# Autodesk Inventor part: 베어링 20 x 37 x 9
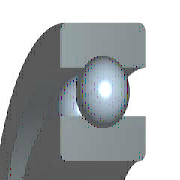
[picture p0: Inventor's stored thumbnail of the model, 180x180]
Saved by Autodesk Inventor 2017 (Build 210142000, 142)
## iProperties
IsCustomPart: 1
Created: 2012-02
Part Number: 베어링 20 x 37 x 9
Material: 강철, 연강
Description: 깊은 그루브 볼 베어링
Document SubType Name: Modeling
Standard: KS B 2023
Designer: mduedu
Standards Organization: KS
Language: ko-KR
Size Designation: 6904 - 20 x 37 x 9
Categories: <MemberInstance><Categories><Category DisplayName="샤프트 부품" InternalName="7f7aeb1f-a693-4053-b835-cee3144e0d98" Mnemonic="SHFT"><Category DisplayName="베어링" Inter
Density: 7.86 g/cm^3
Mass: 36.2613 g
Surface Area: 48.5817 cm^2
Volume: 4.61339 cm^3
Appearance: 노란색
Author: mduedu
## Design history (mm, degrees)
sketch "스케치" dims "d0" = 4.42 (= -0.26 x WD + 0.26 x BD)
  geometry: L1 (2.29, 14.25)-(6.71, 14.25); L2 (4.5, 14.25)-(4.5, 12.04); L3 (4.5, 14.25)-(4.5, 16.46); L4 (2.858, 12.771)-(0, 12.771); L5 (0, 10)-(9, 10); L6 (2.858, 15.729)-(0, 15.729); L7 (0, 18.5)-(9, 18.5); L8 (9, 10)-(9, 12.771); L9 (6.142, 12.771)-(9, 12.771); L10 (6.142, 15.729)-(9, 15.729); L11 (9, 18.5)-(9, 15.729); L12 (-1.4, 0)-(8.4, 0) reference; L13 (0, -0.3)-(0, 5.3) reference
  constraints: 22 end point, 4 point on line, 2 collinear, 2 perpendicular, 2 symmetric about line, 1 midpoint, 1 parallel, 14 other
  dimensions: "d9" = 20 diameter of L5 L12 (= WD); "d11" = 37 diameter of L7 L12 (= BD); "d12" = 9 distance between parallel lines of L8 L13 (= KB); "d13" = 25.542 diameter of L9 L12 (= 0.326 x BD + 0.674 x WD)
revolve "본체" stored, may be unused: angle "d6" = 90 deg
revolve "볼" stored, may be unused: angle "d7" = 90 deg
pattern_circular "IDS_ARRAYBALL[SIMPL:T]" dims angle "d3" = 360 deg
body "Solid1"
fillet "모깎기1" dims "d1" = 0.3 (= KRS)
other parameters: "WD" = 20 [user parameter; used in 5 equation terms], "BD" = 37 [user parameter; used in 5 equation terms], "KB" = 9 [user parameter; used in 1 equation term], "KRS" = 0.3 [user parameter; used in 1 equation term], "d4" = 0, "d5" = 0, "d8" = 0, "d14" = 0, "d15" = 0, "BBA" = 0 [user parameter], "BC0" = 3304000 [user parameter], "BC" = 6184000 [user parameter], "BR" = 18.5 (= 0.5 x BD) [user parameter]
